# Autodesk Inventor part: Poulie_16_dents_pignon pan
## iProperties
Created: 2011-01
Part Number: Poulie_16_dents_pignon pan
Document SubType Name: Modeling
Designer: eric
Density: 1 g/cm^3
Mass: 1.26909 g
Surface Area: 14.1528 cm^2
Volume: 1.26909 cm^3
Author: eric
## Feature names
1. Base1
